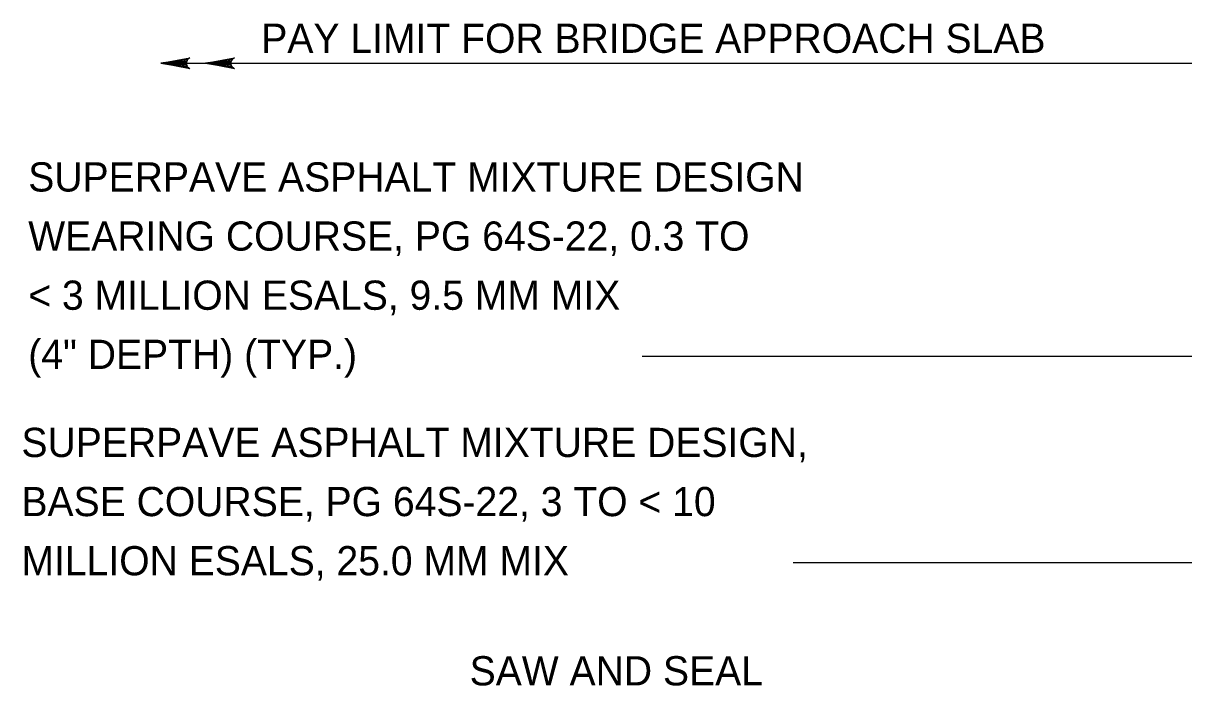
# Model space of a CAD drawing. Extents: x 2084213 to 2099800, y 976677 to 981262.
# Drawn here: x 2094473.3 to 2094864.1, y 979387.4 to 979610.6 of the extents above; entities that cross this region are included whole.
import ezdxf

# ---------------------------------------------------------------- set-up
doc = ezdxf.new("R2010")
doc.units = 0
doc.layers.add('1', color=7, linetype='Continuous')

msp = doc.modelspace()

# ---------------------------------------------------------------- linework, layer by layer
at = {"layer": '1'}
for p, q in [((2094519.68, 979597.06), (2094902.37, 979597.06)), ((2094681.75, 979498.42), (2094918.79, 979498.42)), ((2094732.6, 979428.91), (2094913.65, 979428.91))]:
    msp.add_line(p, q, dxfattribs=at)
for points in [[(2094519.68, 979597.06), (2094529.46, 979598.9), (2094529.09, 979598.63), (2094528.71, 979598.37), (2094528.52, 979598.04), (2094528.32, 979597.72), (2094528.27, 979597.39), (2094528.21, 979597.06), (2094528.27, 979596.73), (2094528.32, 979596.4), (2094528.52, 979596.08), (2094528.71, 979595.75), (2094529.09, 979595.49), (2094529.46, 979595.23), (2094519.68, 979597.06), (2094529.09, 979595.49), (2094528.71, 979595.75), (2094519.68, 979597.06), (2094528.52, 979596.08), (2094528.32, 979596.4), (2094519.68, 979597.06), (2094528.27, 979596.73), (2094528.21, 979597.06), (2094519.68, 979597.06), (2094528.27, 979597.39), (2094528.32, 979597.72), (2094519.68, 979597.06), (2094528.52, 979598.04), (2094528.71, 979598.37), (2094519.68, 979597.06), (2094529.09, 979598.63)], [(2094534.68, 979597.06), (2094544.46, 979598.9), (2094544.09, 979598.63), (2094543.71, 979598.37), (2094543.52, 979598.04), (2094543.32, 979597.72), (2094543.27, 979597.39), (2094543.21, 979597.06), (2094543.27, 979596.73), (2094543.32, 979596.4), (2094543.52, 979596.08), (2094543.71, 979595.75), (2094544.09, 979595.49), (2094544.46, 979595.23), (2094534.68, 979597.06), (2094544.09, 979595.49), (2094543.71, 979595.75), (2094534.68, 979597.06), (2094543.52, 979596.08), (2094543.32, 979596.4), (2094534.68, 979597.06), (2094543.27, 979596.73), (2094543.21, 979597.06), (2094534.68, 979597.06), (2094543.27, 979597.39), (2094543.32, 979597.72), (2094534.68, 979597.06), (2094543.52, 979598.04), (2094543.71, 979598.37), (2094534.68, 979597.06), (2094544.09, 979598.63)]]:
    msp.add_lwpolyline(points, dxfattribs=at)

# ---------------------------------------------------------------- texts
for s, p in [('PAY LIMIT FOR BRIDGE APPROACH SLAB', (2094553.5, 979600.58)), ('SUPERPAVE ASPHALT MIXTURE DESIGN', (2094475.04, 979553.86)), ('WEARING COURSE, PG 64S-22, 0.3 TO', (2094475.04, 979533.94)), ('< 3 MILLION ESALS, 9.5 MM MIX ', (2094475.04, 979514.02)), ('(4" DEPTH) (TYP.)', (2094475.04, 979494.1)), ('SUPERPAVE ASPHALT MIXTURE DESIGN, ', (2094472.75, 979464.42)), ('BASE COURSE, PG 64S-22, 3 TO < 10', (2094472.75, 979444.5)), ('MILLION ESALS, 25.0 MM MIX', (2094472.75, 979424.57)), ('SAW AND SEAL', (2094623.65, 979387.49))]:
    msp.add_text(s, height=9.8425, dxfattribs=at).set_placement(p)

doc.saveas('drawing.dxf')
